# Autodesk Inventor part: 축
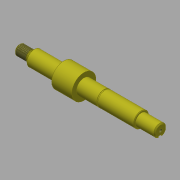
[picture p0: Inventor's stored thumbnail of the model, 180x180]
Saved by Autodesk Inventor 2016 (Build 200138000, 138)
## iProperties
Created: 2016-08
Part Number: 축
Material: 강철, 탄소
Document SubType Name: Modeling
Designer: mduedu
Density: 7.87 g/cm^3
Appearance: 밝은 황색
Author: mduedu
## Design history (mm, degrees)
sketch "스케치1"
  geometry: L1 (-70, 0)-(70, 0); L2 (-70, 0)-(-70, 5); L3 (-70, 5)-(-56, 5); L4 (-56, 5)-(-56, 7.5); L5 (-56, 7.5)-(51, 7.5); L6 (51, 7.5)-(51, 6); L7 (51, 6)-(70, 6); L8 (70, 6)-(70, 0); 2 further points
  constraints: 16 end point, 5 parallel, 2 perpendicular, 1 coincident, 1 horizontal, 1 midpoint
  dimensions: "d0" = 140 distance of L1.start L1.end; "d2" = 14 distance of L2.end L3.end; "d3" = 19 distance of L6.end L7.end; "d4" = 10 diameter of L3 L1; "d5" = 15 diameter of L5 L1; "d6" = 12 diameter of L7 L1
revolve "회전1" sketch "스케치1" stored, may be unused: angle "d7" = 90 deg
sketch "스케치2"
  geometry: L1 (-56, -5)-(-56, 5) reference; L2 (70, -6)-(70, 6) reference; L3 (-56, 0)-(70, 0); L4 (-58, 4.5)-(-58, 5); L5 (-58, 5)-(-56, 5); L6 (-56, 5)-(-56, 4.5); L7 (-58, 4.5)-(-56, 4.5); 1 further point
  constraints: 10 end point, 2 midpoint, 1 parallel, 1 perpendicular, 1 point on line
  dimensions: "d8" = 2 distance of L4.end L5.end; "d10" = 10 diameter of L5 L3; "d11" = 9 diameter of L7 L3
revolve "회전2" sketch "스케치2" stored, may be unused: angle "d12" = 90 deg
node "작업 평면1"
sketch "스케치3"
  geometry: C1 r 12 at (0, 0); 1 further point
  constraints: 1 centre point, 1 coincident
  dimensions: "d15" = 24 diameter of C1
extrude "돌출1" join sketch "스케치3" distance "d16" = 20; taper "d17" = 0 deg
sketch "스케치5"
  geometry: L1 (-70, -5)-(-70, 5) reference; L2 (70, -6)-(70, 6) reference; L3 (-70, 0)-(70, 0); L4 (-6, 7.5)-(51, 7.5) reference; L5 (15.15, 7.5)-(14, 7.5); L6 (14, 7.5)-(14, 7.15); L7 (14, 7.15)-(15.15, 7.15); L8 (15.15, 7.15)-(15.15, 7.5); 1 further point
  constraints: 10 end point, 2 midpoint, 2 parallel, 1 horizontal, 1 perpendicular, 1 point on line
  dimensions: "d19" = 56 distance between parallel lines of L6 L2; "d20" = 1.15 distance between parallel lines of L8 L6; "d21" = 14.3 diameter of L7 L3
revolve "회전3" sketch "스케치5" stored, may be unused: angle "d22" = 90 deg
node "작업 평면3"
sketch "스케치6"
  geometry: L1 (9.5, 7.5)-(9.5, -7.5) reference; L2 (7.5, 2)-(-9.5, 2); L3 (-9.5, 2)-(-9.5, -2); L4 (-9.5, -2)-(7.5, -2); L5 (-9.5, 6)-(-9.5, -6) reference; A1 r 2 centre (7.5, 0) between (7.5, -2) and (7.5, 2); 2 further points
  constraints: 6 end point, 3 tangent, 2 midpoint, 2 point on circle, 1 centre point, 1 horizontal, 1 horizontal alignment, 1 parallel, 1 perpendicular
  dimensions: "d23" = 4 distance between parallel lines of L4 L2
extrude "돌출2" cut sketch "스케치6" distance "d25" = 2.5; taper "d26" = 0 deg
feature "스레드1" dims "d27" = 10, "d28" = 0
chamfer "모따기5" distance "d41" = 0.5; stored, may be unused: second distance "d42" = 2, angle "d43" = 45 deg
chamfer "모따기6" distance "d44" = 0.5; stored, may be unused: second distance "d45" = 2, angle "d46" = 45 deg
chamfer "모따기7" distance "d47" = 1; stored, may be unused: second distance "d48" = 2, angle "d49" = 45 deg
chamfer "모따기8" distance "d50" = 1; stored, may be unused: second distance "d51" = 2, angle "d52" = 45 deg
sketch "스케치8"
  geometry: 1 further point
hole "구멍1" sketch "스케치8" at (2, 3.5) diameter "d53" = 3.242; stored, may be unused: countersink angle "d57" = 90 deg, drill point angle "d59" = 120 deg; dims "d54" = 10, "d55" = 4, "d56" = 2, "d58" = 12
node "솔리드1"
other parameters: "d13" = -44
